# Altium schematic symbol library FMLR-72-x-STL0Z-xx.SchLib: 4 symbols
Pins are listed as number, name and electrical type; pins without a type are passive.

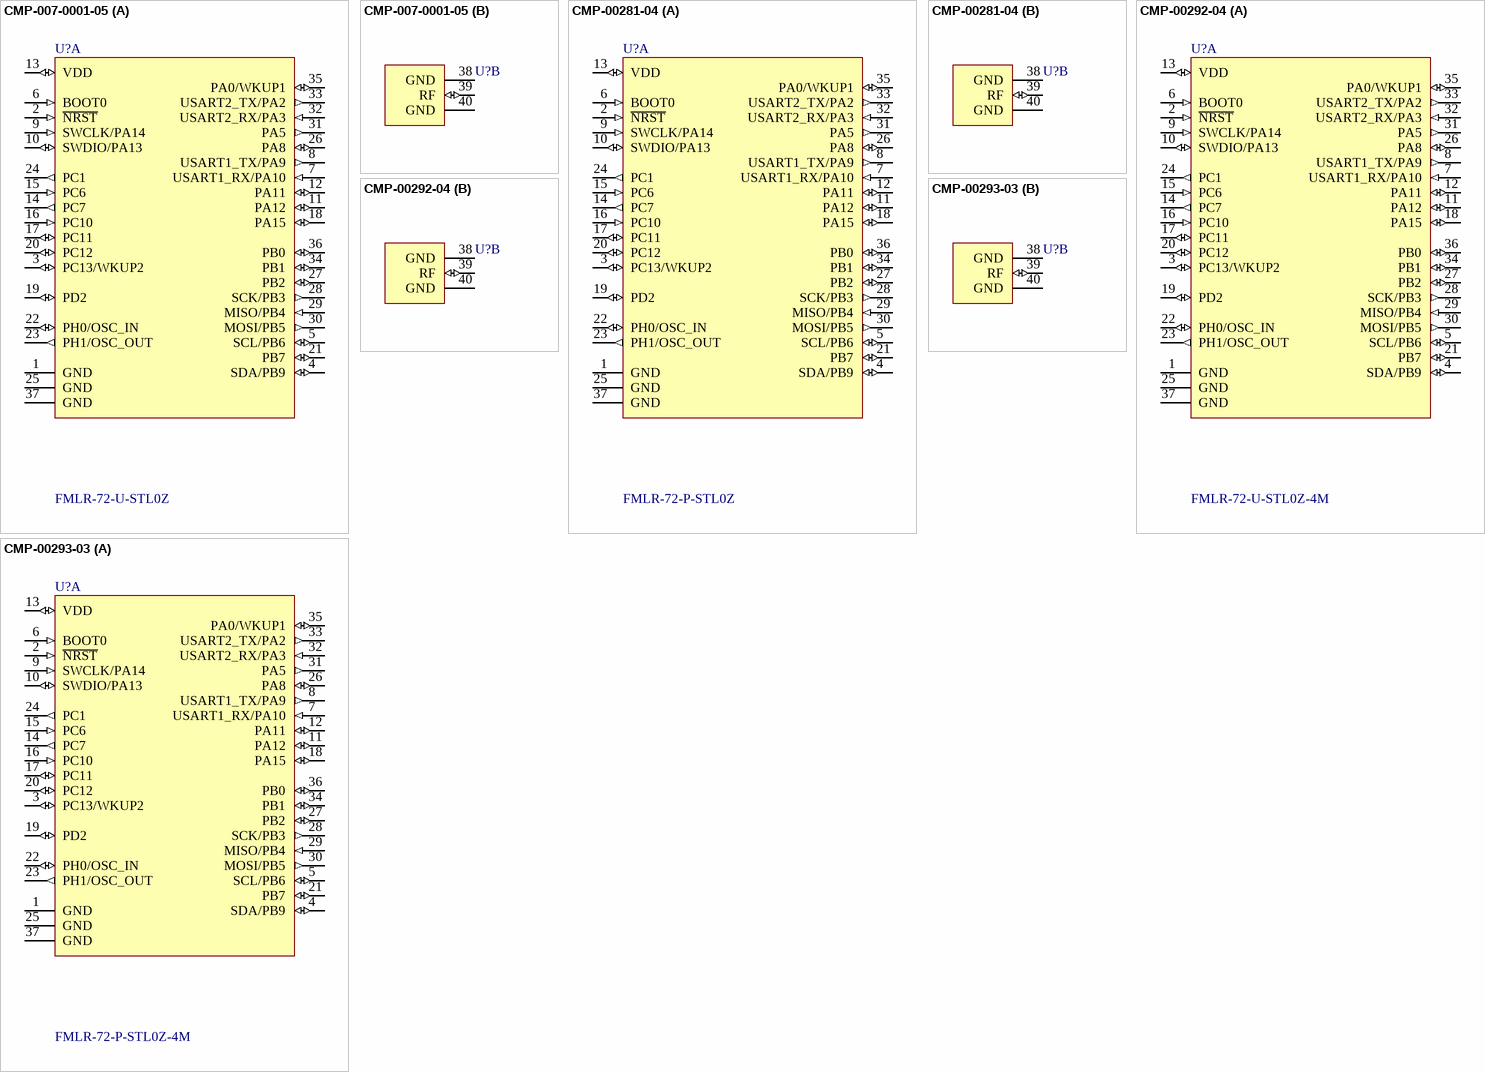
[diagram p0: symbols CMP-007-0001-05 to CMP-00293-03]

## CMP-007-0001-05
designator U?, comment FMLR-72-U-STL0Z
868/915MHz LoRa Module with U.FL connector and STM32L0; Manufacturer: Miromico AG; Manufacturer Part Number: FMLR-U-32L0; Available Preview Images: 2D; Properties: STM32L0, U.FL
footprint FMLR-xx-U-STLx (LoRa Module with ceramic antenna and STM32L0)
footprint FMLR-xx-U-STLx (LoRa Module with ceramic antenna and STM32L0)
part A pins: 1 GND (power), 2 ~{NRST} (in), 3 PC13/WKUP2 (io), 4 SDA/PB9 (io), 5 SCL/PB6 (io), 6 BOOT0 (in), 7 USART1_RX/PA10 (in), 8 USART1_TX/PA9 (out), 9 SWCLK/PA14 (in), 10 SWDIO/PA13 (io), 11 PA12 (io), 12 PA11 (io), 13 VDD (io), 14 PC7 (out), 15 PC6 (in), 16 PC10 (in), 17 PC11 (io), 18 PA15 (io), 19 PD2 (io), 20 PC12 (io), 21 PB7 (io), 22 PH0/OSC_IN (io), 23 PH1/OSC_OUT (out), 24 PC1 (out), 25 GND (power), 26 PA8 (io), 27 PB2 (io), 28 SCK/PB3 (out), 29 MISO/PB4 (in), 30 MOSI/PB5 (out), 31 PA5 (out), 32 USART2_RX/PA3 (in), 33 USART2_TX/PA2 (out), 34 PB1 (io), 35 PA0/WKUP1 (io), 36 PB0 (io), 37 GND (power)
part B pins: 38 GND (power) "Serial Interface Data", 39 RF (io) "Serial Interface Data", 40 GND (power) "Serial Interface Data"

## CMP-00281-04
designator U?, comment FMLR-72-P-STL0Z
868/915MHz LoRa Module with antenna pad and STM32L0; Manufacturer: Miromico AG; Manufacturer Part Number: FMLR-U-32L0; Available Preview Images: 2D; Properties: STM32L0Z
footprint FMLR-xx-U-STLx (LoRa Module with ceramic antenna and STM32L0)
footprint FMLR-xx-U-STLx (LoRa Module with ceramic antenna and STM32L0)
part A pins: 1 GND (power), 2 ~{NRST} (in), 3 PC13/WKUP2 (io), 4 SDA/PB9 (io), 5 SCL/PB6 (io), 6 BOOT0 (in), 7 USART1_RX/PA10 (in), 8 USART1_TX/PA9 (out), 9 SWCLK/PA14 (in), 10 SWDIO/PA13 (io), 11 PA12 (io), 12 PA11 (io), 13 VDD (io), 14 PC7 (out), 15 PC6 (in), 16 PC10 (in), 17 PC11 (io), 18 PA15 (io), 19 PD2 (io), 20 PC12 (io), 21 PB7 (io), 22 PH0/OSC_IN (io), 23 PH1/OSC_OUT (out), 24 PC1 (out), 25 GND (power), 26 PA8 (io), 27 PB2 (io), 28 SCK/PB3 (out), 29 MISO/PB4 (in), 30 MOSI/PB5 (out), 31 PA5 (out), 32 USART2_RX/PA3 (in), 33 USART2_TX/PA2 (out), 34 PB1 (io), 35 PA0/WKUP1 (io), 36 PB0 (io), 37 GND (power)
part B pins: 38 GND (power) "Serial Interface Data", 39 RF (io) "Serial Interface Data", 40 GND (power) "Serial Interface Data"

## CMP-00292-04
designator U?, comment FMLR-72-U-STL0Z-4M
868/915MHz LoRa Module with U.FL connector and STM32L0, 4Mbit flash; Manufacturer: Miromico AG; Manufacturer Part Number: FMLR-U-32L0; Available Preview Images: 2D; Properties: STM32L0, U.FL, 4Mbit flash
footprint FMLR-xx-U-STLx (LoRa Module with ceramic antenna and STM32L0)
footprint FMLR-xx-U-STLx (LoRa Module with ceramic antenna and STM32L0)
part A pins: 1 GND (power), 2 ~{NRST} (in), 3 PC13/WKUP2 (io), 4 SDA/PB9 (io), 5 SCL/PB6 (io), 6 BOOT0 (in), 7 USART1_RX/PA10 (in), 8 USART1_TX/PA9 (out), 9 SWCLK/PA14 (in), 10 SWDIO/PA13 (io), 11 PA12 (io), 12 PA11 (io), 13 VDD (io), 14 PC7 (out), 15 PC6 (in), 16 PC10 (in), 17 PC11 (io), 18 PA15 (io), 19 PD2 (io), 20 PC12 (io), 21 PB7 (io), 22 PH0/OSC_IN (io), 23 PH1/OSC_OUT (out), 24 PC1 (out), 25 GND (power), 26 PA8 (io), 27 PB2 (io), 28 SCK/PB3 (out), 29 MISO/PB4 (in), 30 MOSI/PB5 (out), 31 PA5 (out), 32 USART2_RX/PA3 (in), 33 USART2_TX/PA2 (out), 34 PB1 (io), 35 PA0/WKUP1 (io), 36 PB0 (io), 37 GND (power)
part B pins: 38 GND (power) "Serial Interface Data", 39 RF (io) "Serial Interface Data", 40 GND (power) "Serial Interface Data"

## CMP-00293-03
designator U?, comment FMLR-72-P-STL0Z-4M
868/915MHz LoRa Module with antenna pad and STM32L0, 4Mbit flash; Manufacturer: Miromico AG; Manufacturer Part Number: FMLR-U-32L0; Available Preview Images: 2D
footprint FMLR-xx-U-STLx (LoRa Module with ceramic antenna and STM32L0)
footprint FMLR-xx-U-STLx (LoRa Module with ceramic antenna and STM32L0)
part A pins: 1 GND (power), 2 ~{NRST} (in), 3 PC13/WKUP2 (io), 4 SDA/PB9 (io), 5 SCL/PB6 (io), 6 BOOT0 (in), 7 USART1_RX/PA10 (in), 8 USART1_TX/PA9 (out), 9 SWCLK/PA14 (in), 10 SWDIO/PA13 (io), 11 PA12 (io), 12 PA11 (io), 13 VDD (io), 14 PC7 (out), 15 PC6 (in), 16 PC10 (in), 17 PC11 (io), 18 PA15 (io), 19 PD2 (io), 20 PC12 (io), 21 PB7 (io), 22 PH0/OSC_IN (io), 23 PH1/OSC_OUT (out), 24 PC1 (out), 25 GND (power), 26 PA8 (io), 27 PB2 (io), 28 SCK/PB3 (out), 29 MISO/PB4 (in), 30 MOSI/PB5 (out), 31 PA5 (out), 32 USART2_RX/PA3 (in), 33 USART2_TX/PA2 (out), 34 PB1 (io), 35 PA0/WKUP1 (io), 36 PB0 (io), 37 GND (power)
part B pins: 38 GND (power) "Serial Interface Data", 39 RF (io) "Serial Interface Data", 40 GND (power) "Serial Interface Data"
